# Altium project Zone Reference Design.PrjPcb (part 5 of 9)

## Sheet TPS1214-Q1.SchDoc
size 431 x 279 mm; Date: Not shown in title block; ApprovedBy: Not shown in title block; CheckedBy: Not shown in title block; Author: Not shown in title block; CompanyName: Not shown in title block; Engineer: Not shown in title block; Organization: Not shown in title block; Address1: Not shown in title block; Address2: Not shown in title block; Address3: Not shown in title block; Address4: Not shown in title block; DocumentNumber: 1; Revision: Use project parameter SCH_Rev; SheetNumber: 19; SheetTotal: 30; PageSetup: Record=PageOptions¦CenterHorizontal=True¦CenterVertical=True¦PrintScale=1.00¦XCorrection=1.00¦YCorrection=1.00¦PrintKind=0¦BorderSize=5000000¦LeftOffset=0¦BottomOffset=0¦Orientation=2¦PaperLength=1000¦PaperWidth=1000¦Scale=100¦PaperSource=15¦PrintQuality=600¦MediaType=1¦DitherType=10¦PaperKind=Letter¦PrintScaleMode=1
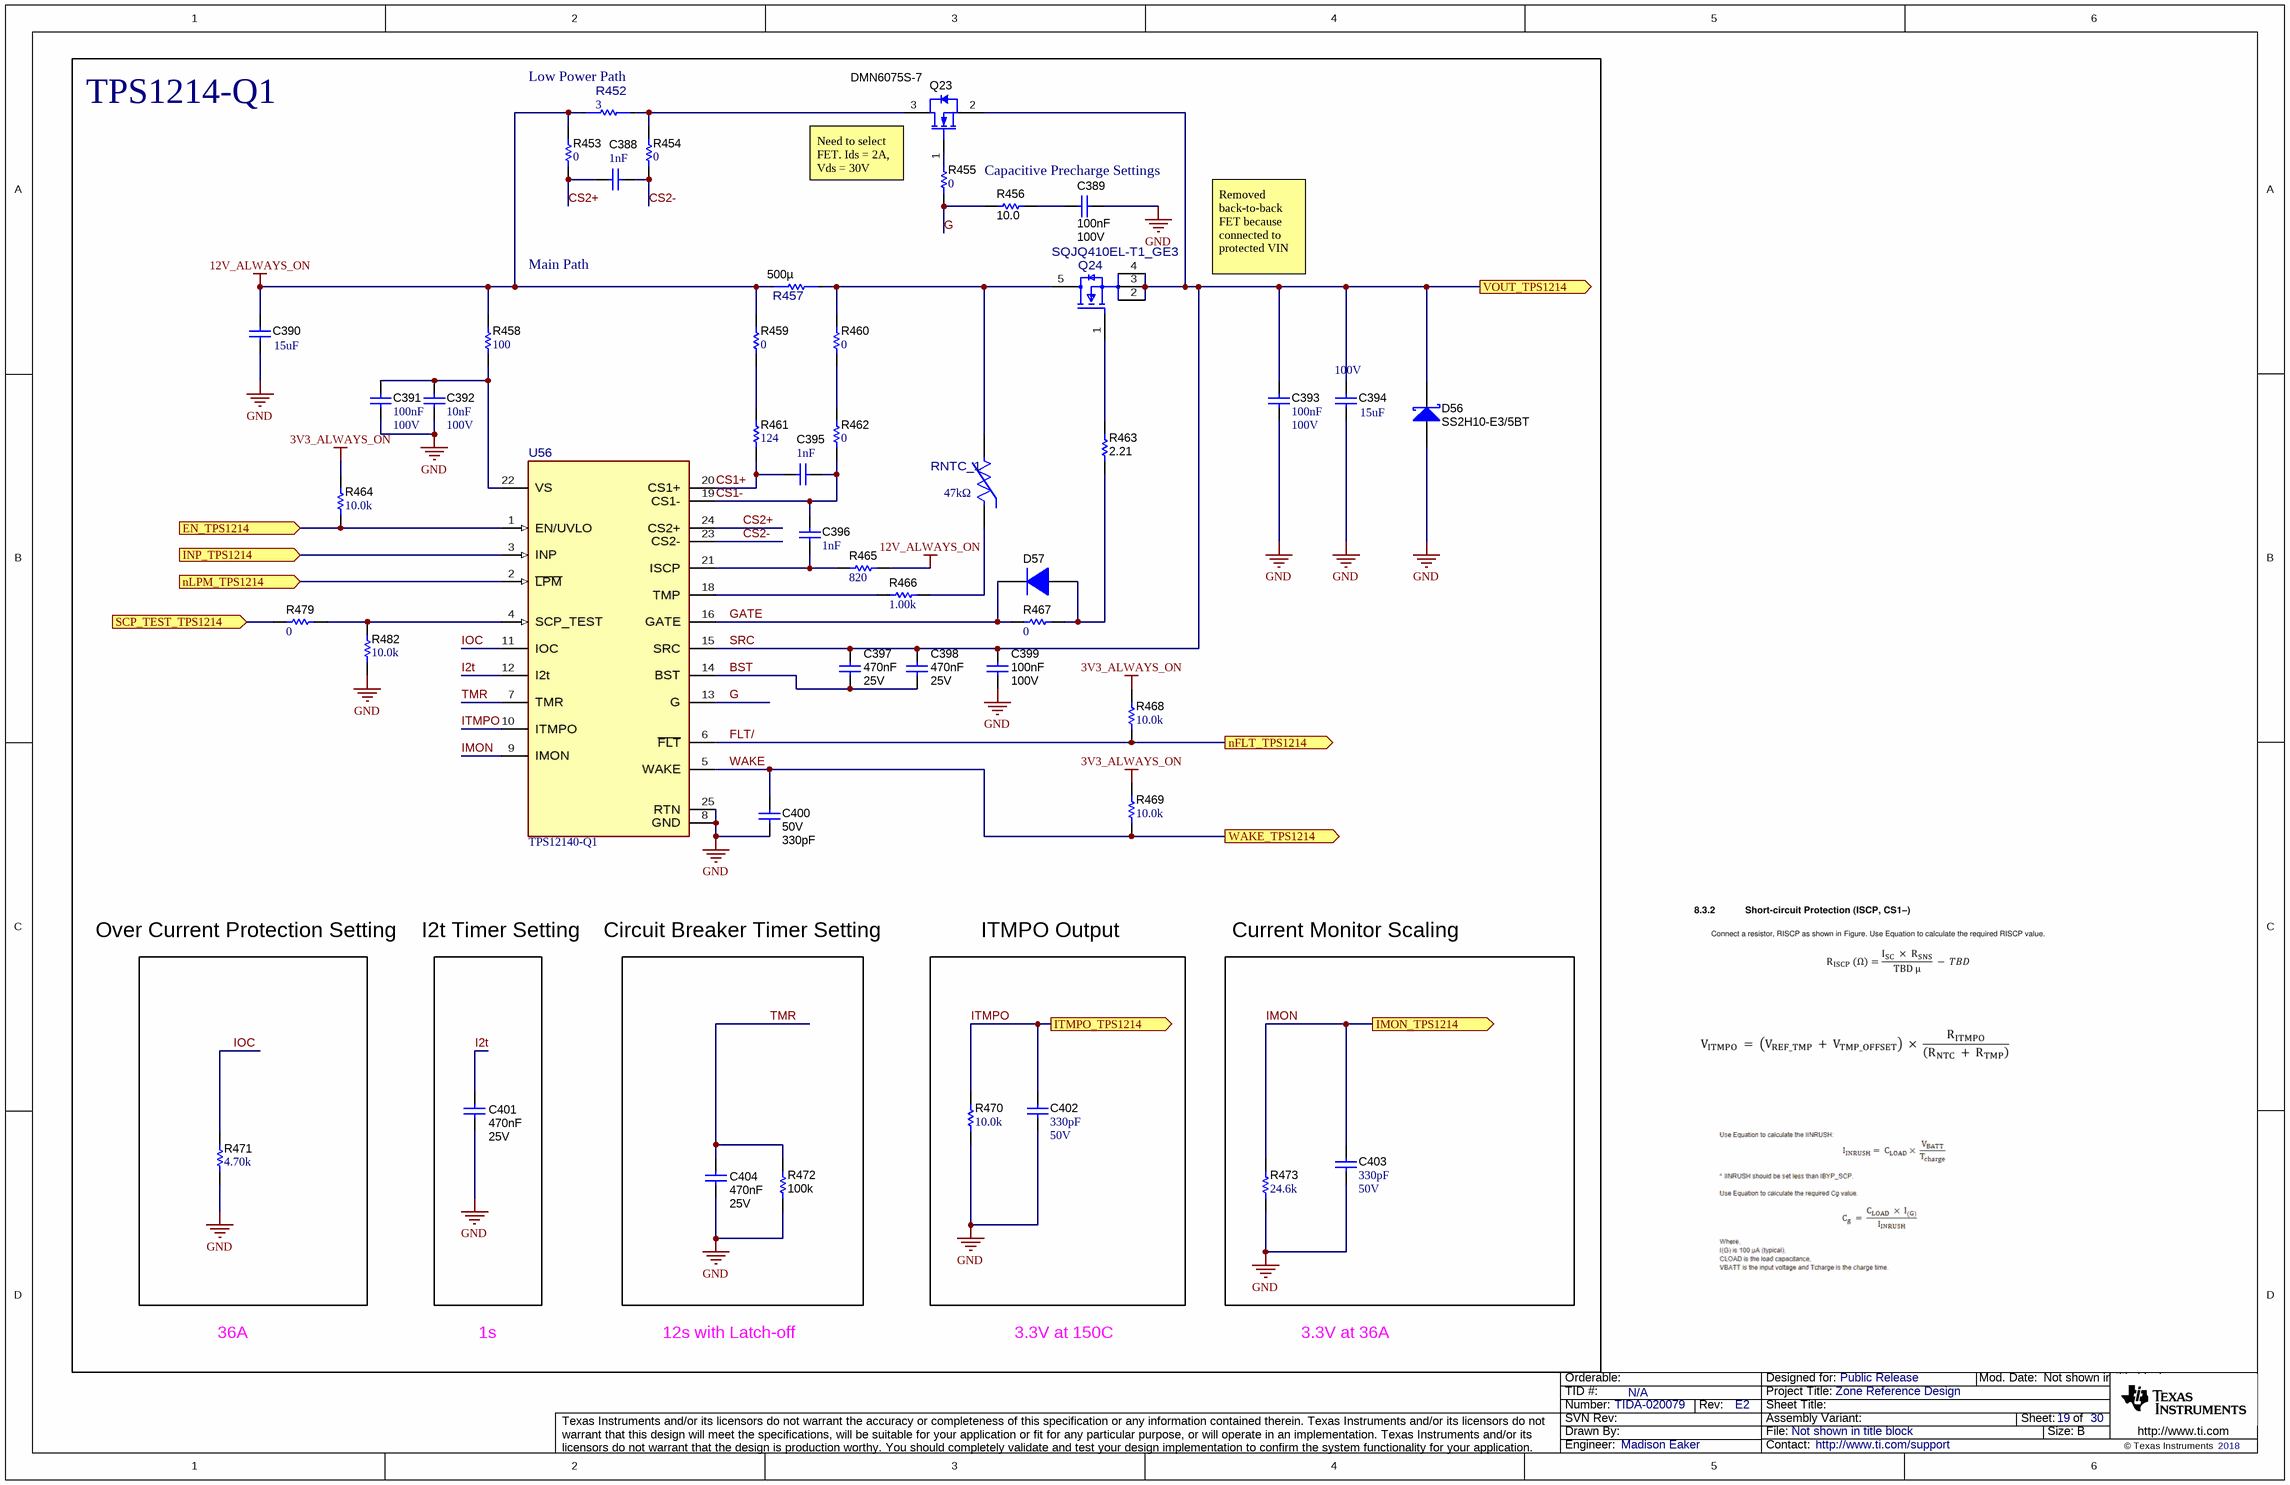
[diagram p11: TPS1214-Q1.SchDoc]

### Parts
C388  Cap_F: 1nF  [0603]  (hidden comment: C0603X102K5RACTU)
C389  Cap_F: 100nF  VDC_V: 100V  [0805_HV]  (hidden comment: CGA4J2X7R2A104K125AA)
C390  ValueDisplayed: 15uF  [KCM55W]  (hidden comment: KCM55WR72A156MH01K)
C391  Cap_F: 100nF  VDC_V: 100V  [0603]  (hidden comment: HMK107B7104KAHT)
C392  Cap_F: 10nF  VDC_V: 100V  [0603]  (hidden comment: CGA3E2X7R2A103K080AA)
C393  Cap_F: 100nF  VDC_V: 100V  [0603]  (hidden comment: HMK107B7104KAHT)
C394  Value2: 100V  ValueDisplayed: 15uF  [KCM55W]  (hidden comment: KCM55WR72A156MH01K)
C395  Cap_F: 1nF  [0603]  (hidden comment: C0603X102K5RACTU)
C396  Cap_F: 1nF  [0603]  (hidden comment: C0603X102K5RACTU)
C397  Cap_F: 470nF  VDC_V: 25V  [0603]  (hidden comment: CGA3E3X7R1E474K080AB)
C398  Cap_F: 470nF  VDC_V: 25V  [0603]  (hidden comment: CGA3E3X7R1E474K080AB)
C399  Cap_F: 100nF  VDC_V: 100V  [0805_HV]  (hidden comment: CGA4J2X7R2A104K125AA)
C400  VDC_V: 50V  ValueDisplayed: 330pF  [0402]  (hidden comment: GRM155R71H331KA01D)
C401  Cap_F: 470nF  VDC_V: 25V  [0603]  (hidden comment: CGA3E3X7R1E474K080AB)
C402  Cap_F: 330pF  VDC_V: 50V  [0603]  (hidden comment: C0603C331K5RACTU)
C403  Cap_F: 330pF  VDC_V: 50V  [0603]  (hidden comment: C0603C331K5RACTU)
C404  Cap_F: 470nF  VDC_V: 25V  [0603]  (hidden comment: CGA3E3X7R1E474K080AB)
D56  SS2H10-E3/5BT  [SMB]
D57  1N4148W-TP  [SOD-123]  (value not drawn)
Q23  DMN6075S-7  [SOT-23]
Q24  SQJQ410EL-T1_GE3  [FP-SQJQ410EL-T1_GE3_PowerPAK 8x8L-MFG]
R452  value 3  [FP-VMP-1R00-1.0-U_2010-MFG]  (hidden comment: VMP-1R00-1.0-U)
R453  ValueDisplayed: 0  [0603]  (hidden comment: CRCW06030000Z0EA)
R454  ValueDisplayed: 0  [0603]  (hidden comment: CRCW06030000Z0EA)
R455  ValueDisplayed: 0  [0603]  (hidden comment: CRCW06030000Z0EA)
R456  ValueDisplayed: 10.0  [0805_HV]  (hidden comment: RC0805FR-0710RL)
R457  Res_ohm: 500µ  [FP-WSL3921L5000FEA_3921-MFG]  (hidden comment: WSL3921L5000FEA)
R458  ValueDisplayed: 100  [0603]  (hidden comment: ERJ-3EKF1000V)
R459  ValueDisplayed: 0  [0603]  (hidden comment: CRCW06030000Z0EA)
R460  ValueDisplayed: 0  [0603]  (hidden comment: CRCW06030000Z0EA)
R461  ValueDisplayed: 124  [0603]  (hidden comment: RC0603FR-07124RL)
R462  ValueDisplayed: 0  [0603]  (hidden comment: CRCW06030000Z0EA)
R463  ValueDisplayed: 2.21  [0603]  (hidden comment: RC0603FR-072R21L)
R464  ValueDisplayed: 10.0k  [TNPW0603]  (hidden comment: TNPW060310K0BEEA)
R465  ValueDisplayed: 820  [0603]  (hidden comment: RC0603FR-07820RL)
R466  ValueDisplayed: 1.00k  [0603]  (hidden comment: RC0603FR-071KL)
R467  ValueDisplayed: 0  [0603]  (hidden comment: CRCW06030000Z0EA)
R468  ValueDisplayed: 10.0k  [TNPW0603]  (hidden comment: TNPW060310K0BEEA)
R469  ValueDisplayed: 10.0k  [TNPW0603]  (hidden comment: TNPW060310K0BEEA)
R470  ValueDisplayed: 10.0k  [0603]  (hidden comment: ERJ-3EKF1002V)
R471  ValueDisplayed: 4.70k  [0603]  (hidden comment: RC0603FR-074K7L)
R472  ValueDisplayed: 100k  [0603]  (hidden comment: CRCW0603100KFKEA)
R473  ValueDisplayed: 24.6k  [0603]  (hidden comment: RT0603BRD0724K6L)
R479  ValueDisplayed: 0  [0603]  (hidden comment: RC0603JR-070RL)
R482  ValueDisplayed: 10.0k  [TNPW0603]  (hidden comment: TNPW060310K0BEEA)
RNTC_1  value 47kΩ  [FP-NCU18WB473J6SRB_0603-MFG]  (hidden comment: NCU18WB473J6SRB)
U56  TPS12140-Q1  [RGE0023A-MFG]

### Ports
EN_TPS1214 (in), IMON_TPS1214 (out), INP_TPS1214 (in), ITMPO_TPS1214 (out), nFLT_TPS1214 (out), nLPM_TPS1214 (in), SCP_TEST_TPS1214 (in), VOUT_TPS1214 (out), WAKE_TPS1214 (out)

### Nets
3V3_ALWAYS_ON: R464.2 R468.2 R469.2
12V_ALWAYS_ON: C390.1 R452.1 R453.2 R457.1 R458.2 R459.2 R465.2
GND: C389.2 C390.2 C391.2 C392.2 C393.2 C394.2 C399.2 C400.2 C401.2 C402.2 C403.2 C404.2 D56.2(A) R470.2 R471.1 R472.1 R473.1 R482.1 U56.8(GND) U56.25(RTN)
BST: C397.2 C398.2 U56.14(BST)  [project net BST_19]
CS1+: C395.2 R461.1 U56.20(CS1+)  [project net CS1+_19]
CS1-: C395.1 C396.1 R462.1 U56.19(CS1-)  [project net CS1-_19]
CS2+: C388.2 R453.1 U56.24(CS2+)  [project net CS2+_19]
CS2-: C388.1 R454.1 U56.23(CS2-)  [project net CS2-_19]
EN_TPS1214: R464.1 U56.1(EN/UVLO) ; port EN_TPS1214
EPWM_15A: R479.1 ; port SCP_TEST_TPS1214
FLT/: R468.1 U56.6(~{FLT}) ; port nFLT_TPS1214
G: R455.1 R456.2 U56.13(G)  [project net G_19]
GATE: D57.1(K) R467.2 U56.16(GATE)  [project net GATE_19]
GPIO79: U56.3(INP) ; port INP_TPS1214
GPIO107: U56.2(~{LPM}) ; port nLPM_TPS1214
I2t: C401.1 U56.12(I2t)  [project net I2t_19]
IMON: C403.1 R473.2 U56.9(IMON) ; port IMON_TPS1214
IOC: R471.2 U56.11(IOC)  [project net IOC_19]
ITMPO: C402.1 R470.1 U56.10(ITMPO) ; port ITMPO_TPS1214
SRC: C393.1 C394.1 C397.1 C398.1 C399.1 D56.1(K) Q23.2(S) Q24.2(S) Q24.3(S) Q24.4(S) U56.15(SRC) ; port VOUT_TPS1214
TMR: C404.1 R472.2 U56.7(TMR)  [project net TMR_19]
WAKE: C400.1 R469.1 U56.5(WAKE) ; port WAKE_TPS1214
NetC389_1: C389.1 R456.1
NetC391_1: C391.1 C392.1 R458.1 U56.22(VS)
NetC396_2: C396.2 R465.1 U56.21(ISCP)
NetD57_2: D57.2(A) R463.1 R467.1
NetQ23_1: Q23.1(G) R455.2
NetQ23_3: Q23.3(D) R452.2 R454.2
NetQ24_1: Q24.1(G) R463.2
NetQ24_5: Q24.5(D) R457.2 R460.2 RNTC_1.2
NetR459_1: R459.1 R461.2
NetR460_1: R460.1 R462.2
NetR466_1: R466.1 U56.18(TMP)
NetR466_2: R466.2 RNTC_1.1
NetR479_2: R479.2 R482.2 U56.4(SCP_TEST)

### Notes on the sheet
- (near R452) Low Power Path
- TPS1214-Q1
- Need to select FET. Ids = 2A, Vds = 30V
- Capacitive Precharge Settings
- Main Path
- Removed back-to-back FET because connected to protected VIN
- Over Current Protection Setting
- I2t Timer Setting
- Circuit Breaker Timer Setting
- ITMPO Output
- Current Monitor Scaling
- 36A
- 1s
- 12s with Latch-off
- 3.3V at 150C
- 3.3V at 36A

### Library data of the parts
C388 C395 C396 = CMP-0006976-5: CAP, CERM, 1000 pF, 50 V, +/- 10%, X7R, 0603; Manufacturer: Kemet; TaMin_C: -55°C; Polarized: N; SizeAreaWB_mm2: 4.68; Value1: Unknown; U/M: EA; Value: 1000pF; TaMax_C: 125°C; SizeZ_mm: 1; SizeX_mm: 1.6; SizeY_mm: 0.8; Value2: 50V; SizeArea_mm2: 1.28; AEC Category: Q200
C389 C399 = CMP-0007969-2: CAP, CERM, 0.1 uF, 100 V, +/- 10%, X7R, AEC-Q200 Grade 1, 0805; Manufacturer: TDK; TaMin_C: -55°C; ESR_ohm: 0.020726; Polarized: N; SizeAreaWB_mm2: 6.75; Value1: 0.020726 ohm; U/M: EA; Value: 0.1uF; TaMax_C: 125°C; SizeZ_mm: 1.45; SizeX_mm: 2; SizeY_mm: 1.25; Cap_Case: 0805; SizeArea_mm2: 2.5; AEC Qualified: Y; IRMS_A: 1.456A; AEC Grade: 1; AEC Category: Q200
C390 = CMP-0009477-2: CAP, CERM, 15 uF, 100 V, +/- 20%, X7R, Stacked 2220; Manufacturer: MuRata; TaMin_C: -55°C; Polarized: N; SizeAreaWB_mm2: 59.13; Value1: Unknown; U/M: EA; Value: 15uF; TaMax_C: 125°C; SizeZ_mm: 6.7; SizeX_mm: 6.1; SizeY_mm: 5.3; Cap_Case: 2220; Value2: 100V; SizeArea_mm2: 32.33; Cap_F: 15µF; AEC Category: Q200
C391 C393 = CMP-0081011-1: CAP, CERM, 0.1 µF, 100 V,+/- 10%, X7R, AEC-Q200 Grade 1, 0603; Manufacturer: Taiyo Yuden; SizeAreaWB_mm2: 4.68; SizeArea_mm2: 1.28; AEC Qualified: Y; AEC Category: Q200; Value: 0.1uF; TaMax_C: 125°C; SizeZ_mm: 1; Polarized: N; TaMin_C: -55°C; SizeY_mm: 0.8; U/M: EA; SizeX_mm: 1.6; ValueDisplayed: 0.1µF
C392 = CMP-0007082-4: CAP, CERM, 0.01 uF, 100 V, +/- 10%, X7R, AEC-Q200 Grade 1, 0603; Manufacturer: TDK; TaMin_C: -55°C; ESR_ohm: 0.2354; Polarized: N; SizeAreaWB_mm2: 4.68; Value1: 0.235428 ohm; U/M: EA; Value: 0.01uF; TaMax_C: 125°C; SizeZ_mm: 1; SizeX_mm: 1.6; SizeY_mm: 0.8; SizeArea_mm2: 1.28; AEC Qualified: Y; IRMS_A: 396.995mA; AEC Category: Q200
C394 = CMP-0009477-2: CAP, CERM, 15 uF, 100 V, +/- 20%, X7R, Stacked 2220; Manufacturer: MuRata; TaMin_C: -55°C; Polarized: N; SizeAreaWB_mm2: 59.13; Value1: Unknown; U/M: EA; Value: 15uF; TaMax_C: 125°C; SizeZ_mm: 6.7; SizeX_mm: 6.1; SizeY_mm: 5.3; Cap_Case: 2220; SizeArea_mm2: 32.33; Cap_F: 15µF; AEC Category: Q200
C397 C398 C401 C404 = CMP-0007092-5: CAP, CERM, 0.47 uF, 25 V, +/- 10%, X7R, AEC-Q200 Grade 1, 0603; Manufacturer: TDK; TaMin_C: -55°C; Polarized: N; SizeAreaWB_mm2: 4.68; Value1: Unknown; U/M: EA; Value: 0.47uF; TaMax_C: 125°C; SizeZ_mm: 1; SizeX_mm: 1.6; SizeY_mm: 0.8; SizeArea_mm2: 1.28; AEC Qualified: Y; AEC Category: Q200
C400 = CMP-0006687-2: CAP, CERM, 330 pF, 50 V, +/- 10%, X7R, 0402; Manufacturer: MuRata; TaMin_C: -55°C; Polarized: N; SizeAreaWB_mm2: 3; Value1: Unknown; U/M: EA; Value: 330pF; TaMax_C: 125°C; SizeZ_mm: 0.6; SizeX_mm: 1; SizeY_mm: 0.5; AEC Category: Q200
C402 C403 = CMP-0006921-4: CAP, CERM, 330 pF, 50 V, +/- 10%, X7R, 0603; Manufacturer: Kemet; TaMin_C: -55°C; Polarized: N; SizeAreaWB_mm2: 4.68; Value1: Unknown; U/M: EA; Value: 330pF; TaMax_C: 125°C; SizeZ_mm: 1; SizeX_mm: 1.6; SizeY_mm: 0.8; SizeArea_mm2: 1.28; AEC Category: Q200
D56 = CMP-0028987-2: Diode, Schottky, 100 V, 2 A, SMB; Manufacturer: Vishay-Semiconductor; Vf_V: 790mV; AEC Qualified: N; SizeArea_mm2: 21.336; Value: 100V; SizeX_mm: 5.6; Value1: 2A; Value2: 0.79V; SizeZ_mm: 2.6; SizeAreaWB_mm2: 44.156; AEC Category: Q101; TJmax_C: 175°C; SizeY_mm: 3.81
D57 = CMP-0076974-1: Diode, Switching, 100 V, 0.15 A, SOD-123; Manufacturer: Micro Commercial Components; SizeAreaWB_mm2: 13.095; Vr_V: 100V; SizeArea_mm2: 6.545; TJmax_C: 150°C; AEC Category: Q101; Value: 100V; SizeZ_mm: 1.35; Green_REACh: Incomplete; Io_A: 150mA; Vf_V: 1.25V; SizeY_mm: 1.7; Green_Lifecycle: Not Set; U/M: EA; Value1: 0.15A; SizeX_mm: 3.85
Q23 = CMP-0078323-1: MOSFET, N-CH, 60 V, 2 A, AEC-Q101, SOT-23; Manufacturer: Diodes Inc.; Alternate Manufacturer: None; ChType: N; QgTyp_nC: 5.6; SizeAreaWB_mm2: 14; SizeArea_mm2: 7.5; IdsMax_A: 2A; AEC Qualified: Y; VdsMax_V: 60V; Rdson45_ohm: 0.12; Vgs_V: 20V; AEC Category: Q101; Value: 60V; SizeZ_mm: 1.1; SizeY_mm: 3; Value2: 5.6 nC; U/M: EA; Value1: 0.12 ohm; SizeX_mm: 2.5
Q24 = CMP-0091832-1: N-Channel 100V 135A (Tc) 136W (Tc) Surface Mount PowerPAK® 8 x 8; Manufacturer: Vishay; Rthja Max: 50°C/W; Rdson45_ohm: 2.8m; AEC Qualified: Yes; QgTyp_nC: 97nC @ 10V; Standoff Height: 0mm; Input Capacitace At Vds: 5620pF @ 25V; Threshold Vgs Min: 1.5V; SizeZ_mm: 2.03mm; Turn On Delay Time: 19ns; Typ Forward Diode Voltage: 0.83V; TJmax_C: +175°C; AEC Grade: Grade 0; Transconductance: 84S; Number Of N Channels: 1; Turn Off Delay Time: 69ns; Pulse Drain Current: 210A; ChMode: False; Threshold Vgs Max: 2.5V; Vgs_V: 20V; VdsMax_V: 1.2V
R452 = CMP-0098465-1: 1 Ohms ±1% 3W Chip Resistor 2010 (5025 Metric) Automotive AEC-Q200, Current Sense, Moisture Resistant, Pulse Withstanding; Manufacturer: Isabellenhuette; AEC Grade: Grade 0; AEC Qualified: Yes; Res_ohm: 1; SizeZ_mm: 0.55mm; TempCo: 20ppm/°C
R453-R455 R459 R460 R462 R467 = CMP-0025697-4: RES, 0, 5%, 0.1 W, AEC-Q200 Grade 0, 0603; Manufacturer: Vishay-Dale; Power_W: 100mW; TempCo: 200 ppm/C; Value_Code: 0000; Value: 0; EIA_Code: E24; SizeX_mm: 1.6; SizeY_mm: 0.8; SizeZ_mm: 1; Value2: 0.1W; SizeArea_mm2: 1.28; CompType: Resistor; AEC Qualified: Y; VDC_V: 75V; AEC Category: Q200
R456 = CMP-0021863-2: RES, 10.0, 1%, 0.125 W, 0805; Manufacturer: Yageo America; Power_W: 125mW; TempCo: 200 ppm/C; Value_Code: 10R0; U/M: EA; Value: 10.0; EIA_Code: E96; Res_ohm: 10; SizeX_mm: 2; SizeY_mm: 1.25; SizeZ_mm: 1.45; Value2: 0.125W; SizeArea_mm2: 2.5; VDC_V: 150V; AEC Category: Q200
R457 = CMP-0092921-1: Res Metal Strip 3921 0.0005 Ohm 1% 3W ±175ppm/°C Molded SMD SMD Embossed Plastic T/R; Manufacturer: Vishay Dale; Value: 500µ; TempCo: 150ppm/°C; SizeZ_mm: 0.05inch; AEC Qualified: Yes; AEC Grade: Grade 0
R458 = CMP-0022679-3: RES, 100, 1%, 0.1 W, AEC-Q200 Grade 0, 0603; Manufacturer: Panasonic; Power_W: 100mW; TempCo: 100 ppm/C; Value_Code: 100R; U/M: EA; Value: 100; EIA_Code: E96; SizeX_mm: 1.6; SizeY_mm: 0.8; SizeZ_mm: 1; Value2: 0.1W; SizeArea_mm2: 1.28; AEC Qualified: Y; AEC Grade: 0; AEC Category: Q200
R461 = CMP-0022773-5: RES, 124, 1%, 0.1 W, 0603; Manufacturer: Yageo; Power_W: 100mW; TempCo: 100 ppm/C; Value_Code: 124R; Value: 124; EIA_Code: E96; SizeX_mm: 1.6; SizeY_mm: 0.8; SizeZ_mm: 1; Value2: 0.1W; SizeArea_mm2: 1.28; AEC Qualified: N; VDC_V: 75V; AEC Category: Q200; SizeAreaWB_mm2: 4.68
R463 = CMP-0023007-4: RES, 2.21, 1%, 0.1 W, 0603; Manufacturer: Yageo; Power_W: 100mW; TempCo: 200 ppm/C; Value_Code: 2R21; Value: 2.21; EIA_Code: E96; SizeX_mm: 1.6; SizeY_mm: 0.8; SizeZ_mm: 1; Value2: 0.1W; SizeArea_mm2: 1.28; AEC Qualified: N; VDC_V: 75V; AEC Category: Q200; SizeAreaWB_mm2: 4.68
R464 R468 R469 R482 = CMP-0025686-1: RES, 10.0 k, 0.1%, 0.1 W, AEC-Q200 Grade 1, 0603; Manufacturer: Vishay-Dale; Power_W: 100mW; TempCo: 25 ppm/C; Value_Code: 10k0; U/M: EA; Value: 10.0k; EIA_Code: E192; Res_ohm: 10k; SizeX_mm: 1.6; SizeY_mm: 0.85; SizeZ_mm: 0.55; Value2: 0.1W; SizeArea_mm2: 1.36; AEC Qualified: Y; VDC_V: 75V; AEC Grade: 1; AEC Category: Q200
R465 = CMP-0023288-5: RES, 820, 1%, 0.1 W, 0603; Manufacturer: Yageo; Power_W: 100mW; TempCo: 100 ppm/C; Value_Code: 820R; Value: 820; SizeX_mm: 1.6; SizeY_mm: 0.8; SizeZ_mm: 1; Value2: 0.1W; SizeArea_mm2: 1.28; AEC Qualified: N; VDC_V: 75V; AEC Category: Q200; SizeAreaWB_mm2: 4.68
R466 = CMP-0022895-5: RES, 1.00 k, 1%, 0.1 W, 0603; Manufacturer: Yageo; Power_W: 100mW; TempCo: 100 ppm/C; Value_Code: 1k00; Value: 1.00k; EIA_Code: E96; Res_ohm: 1k; SizeX_mm: 1.6; SizeY_mm: 0.8; SizeZ_mm: 1; Value2: 0.1W; SizeArea_mm2: 1.28; AEC Qualified: N; VDC_V: 75V; AEC Category: Q200; SizeAreaWB_mm2: 4.68
R470 = CMP-0022684-2: RES, 10.0 k, 1%, 0.1 W, 0603; Manufacturer: Panasonic; Power_W: 100mW; TempCo: 100 ppm/C; Value_Code: 10k0; U/M: EA; Value: 10.0k; EIA_Code: E96; Res_ohm: 10k; SizeX_mm: 1.6; SizeY_mm: 0.8; SizeZ_mm: 1; Value2: 0.1W; SizeArea_mm2: 1.28; VDC_V: 75V; AEC Category: Q200
R471 = CMP-0023153-5: RES, 4.70 k, 1%, 0.1 W, 0603; Manufacturer: Yageo; Power_W: 100mW; TempCo: 100 ppm/C; Value_Code: 4k70; Value: 4.70k; Res_ohm: 4.7k; SizeX_mm: 1.6; SizeY_mm: 0.8; SizeZ_mm: 1; Value2: 0.1W; SizeArea_mm2: 1.28; AEC Qualified: N; VDC_V: 75V; AEC Category: Q200; SizeAreaWB_mm2: 4.68
R472 = CMP-0021990-4: RES, 100 k, 1%, 0.1 W, AEC-Q200 Grade 0, 0603; Manufacturer: Vishay-Dale; Power_W: 100mW; TempCo: 100 ppm/C; Value: 100k; EIA_Code: E96; SizeX_mm: 1.6; SizeY_mm: 0.8; SizeZ_mm: 1; Value2: 0.1W; SizeArea_mm2: 1.28; AEC Qualified: Y; VDC_V: 75V; AEC Category: Q200; AEC Grade: 0
R473 = CMP-0023989-3: RES, 24.6 k, 0.1%, 0.1 W, 0603; Manufacturer: Yageo America; Power_W: 100mW; TempCo: 25 ppm/C; Value_Code: 24k6; U/M: EA; Value: 24.6k; EIA_Code: E192; SizeX_mm: 1.6; SizeY_mm: 0.8; SizeZ_mm: 1; Value2: 0.1W; SizeArea_mm2: 1.28; VDC_V: 75V; AEC Category: Q200
R479 = CMP-0025885-5: RES, 0, 5%, 0.1 W, 0603; Manufacturer: Yageo; Power_W: 100mW; TempCo: 200 ppm/C; Value_Code: 0000; Value: 0; EIA_Code: E24; SizeX_mm: 1.6; SizeZ_mm: 1; Value2: 0.1W; SizeArea_mm2: 1.28; AEC Qualified: N; VDC_V: 75V; AEC Category: Q200; SizeY_mm: 0.8; SizeAreaWB_mm2: 4.68
RNTC_1 = CMP-0095715-1: NTC Thermistor for Temperature Sensor, Automotive, 0603, 47kΩ, 5%, 0.046mA, 5V; Manufacturer: Murata; B 25 50: 4050K; B 25 100: 4131K; SizeZ_mm: 0.95mm; AEC Qualified: Yes; B 25 85: 4108K; B Tolerance: 1%; Automotive Grade: Grade 0
U56 = CMP-0121394-1: Low IQ Smart High Side gate driver with I2t, Low Power Mode and Diagnostics; Manufacturer: Texas Instruments; SizeZ_mm: 1mm; Standoff Height: 0mm

## Sheet CAN-LIN Overview.SchDoc
size 431 x 279 mm; Date: Not shown in title block; ApprovedBy: Not shown in title block; CheckedBy: Not shown in title block; Author: Not shown in title block; CompanyName: Not shown in title block; Engineer: Not shown in title block; Organization: Not shown in title block; Address1: Not shown in title block; Address2: Not shown in title block; Address3: Not shown in title block; Address4: Not shown in title block; DocumentNumber: 1; Revision: Use project parameter SCH_Rev; SheetNumber: 20; SheetTotal: 30; PageSetup: Record=PageOptions¦CenterHorizontal=True¦CenterVertical=True¦PrintScale=1.00¦XCorrection=1.00¦YCorrection=1.00¦PrintKind=0¦BorderSize=5000000¦LeftOffset=0¦BottomOffset=0¦Orientation=2¦PaperLength=1000¦PaperWidth=1000¦Scale=100¦PaperSource=15¦PrintQuality=600¦MediaType=1¦DitherType=10¦PaperKind=Letter¦PrintScaleMode=1
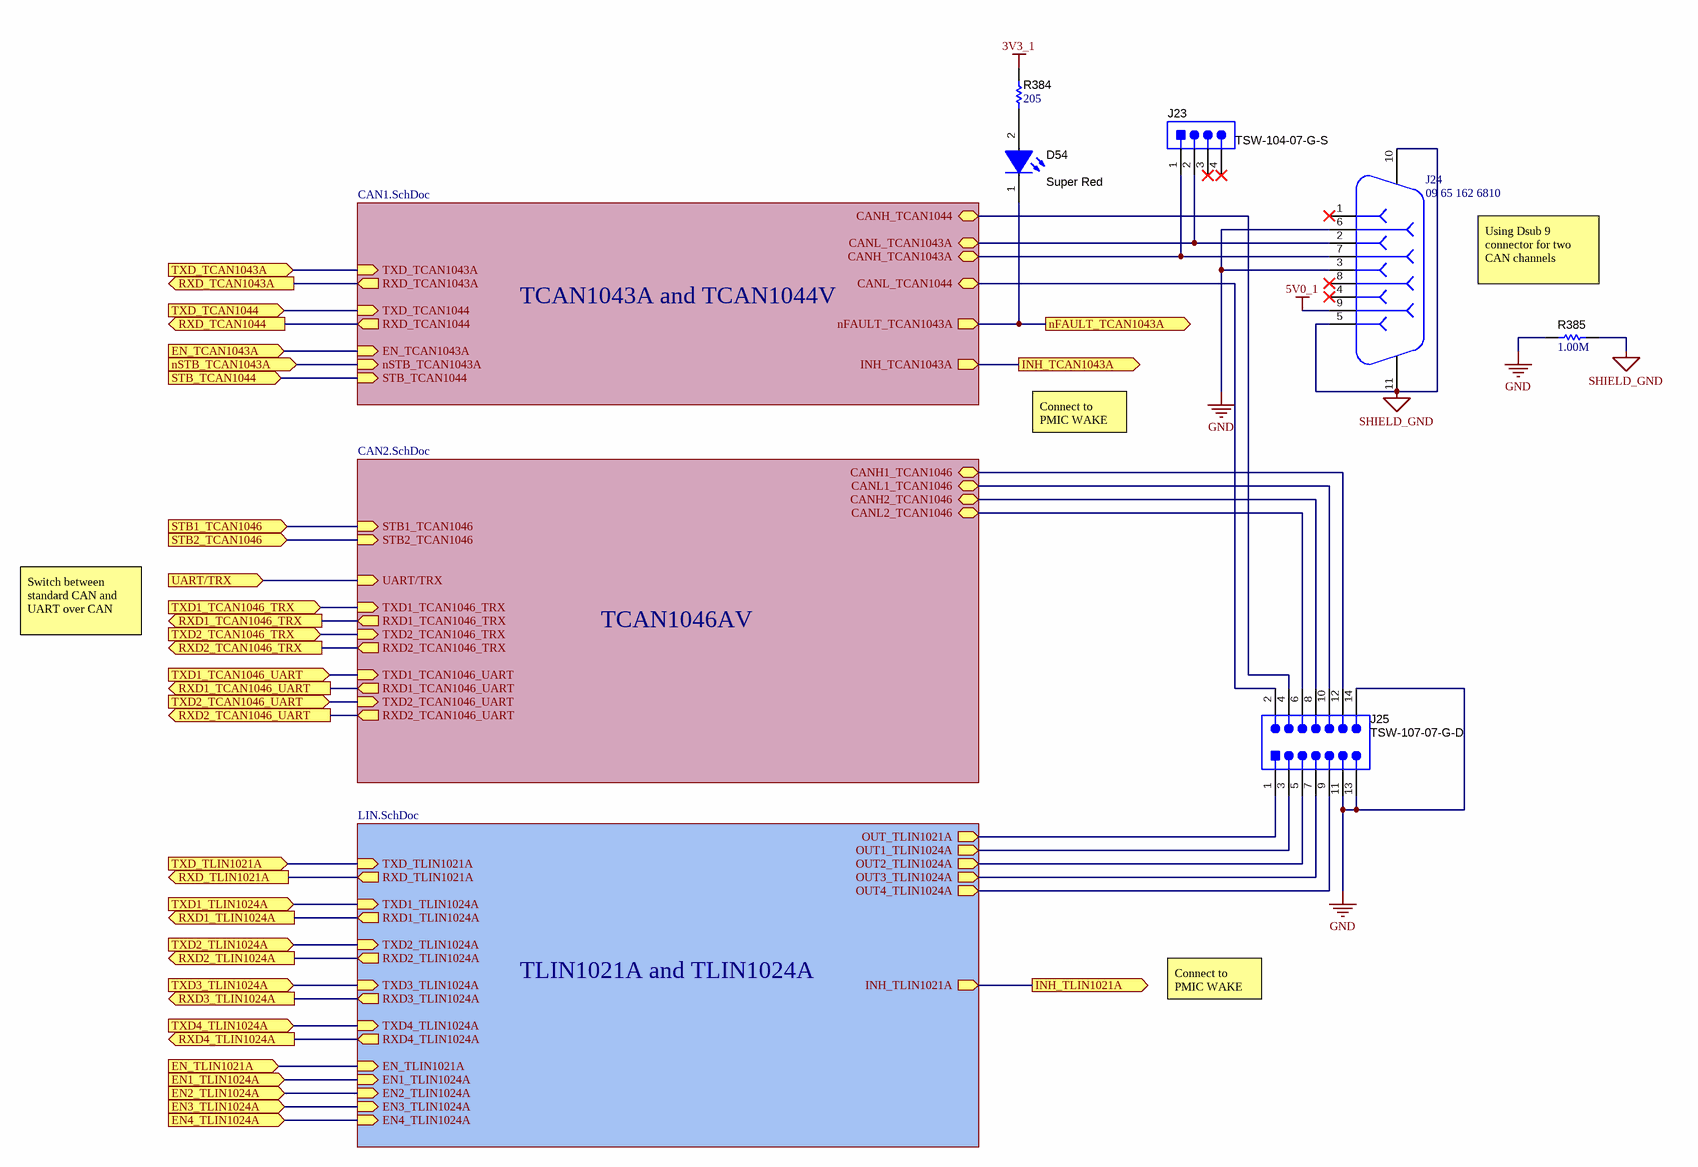
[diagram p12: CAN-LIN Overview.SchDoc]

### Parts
D54  value Super Red  [WL-SMCW_RED]  (hidden comment: 150060SS75000)
J23  TSW-104-07-G-S  [TSW-104-07-G-S]
J24  09 65 162 6810  [Harting_09 65 162 6810]
J25  TSW-107-07-G-D  [TSW-107-07-X-D]
R384  ValueDisplayed: 205  [0603]  (hidden comment: RC0603FR-07205RL)
R385  ValueDisplayed: 1.00M  [0603]  (hidden comment: MCT06030C1004FP500)

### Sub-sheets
TCAN1043A and TCAN1044V = CAN1.SchDoc: TXD_TCAN1044 (in), RXD_TCAN1044 (out), STB_TCAN1044 (in), TXD_TCAN1043A (in), INH_TCAN1043A (out), nFAULT_TCAN1043A (out), nSTB_TCAN1043A (in), EN_TCAN1043A (in), RXD_TCAN1043A (out), CANH_TCAN1043A (bidir), CANL_TCAN1043A (bidir), CANH_TCAN1044 (bidir), CANL_TCAN1044 (bidir)
TCAN1046AV = CAN2.SchDoc: STB1_TCAN1046 (in), STB2_TCAN1046 (in), TXD1_TCAN1046_UART (in), TXD1_TCAN1046_TRX (in), RXD1_TCAN1046_UART (out), RXD1_TCAN1046_TRX (out), TXD2_TCAN1046_UART (in), TXD2_TCAN1046_TRX (in), RXD2_TCAN1046_UART (out), RXD2_TCAN1046_TRX (out), UART/TRX (in), CANH1_TCAN1046 (bidir), CANL1_TCAN1046 (bidir), CANH2_TCAN1046 (bidir), CANL2_TCAN1046 (bidir)
TLIN1021A and TLIN1024A = LIN.SchDoc: EN_TLIN1021A (in), TXD_TLIN1021A (in), RXD_TLIN1021A (out), INH_TLIN1021A (out), EN1_TLIN1024A (in), EN2_TLIN1024A (in), RXD1_TLIN1024A (out), RXD2_TLIN1024A (out), TXD1_TLIN1024A (in), TXD2_TLIN1024A (in), RXD3_TLIN1024A (out), RXD4_TLIN1024A (out), TXD3_TLIN1024A (in), TXD4_TLIN1024A (in), EN3_TLIN1024A (in), EN4_TLIN1024A (in), OUT_TLIN1021A (out), OUT1_TLIN1024A (out), OUT2_TLIN1024A (out), OUT3_TLIN1024A (out), OUT4_TLIN1024A (out)

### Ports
EN1_TLIN1024A (in), EN2_TLIN1024A (in), EN3_TLIN1024A (in), EN4_TLIN1024A (in), EN_TCAN1043A (in), EN_TLIN1021A (in), INH_TCAN1043A (out), INH_TLIN1021A (out), nFAULT_TCAN1043A (out), nSTB_TCAN1043A (in), RXD1_TCAN1046_TRX (out), RXD1_TCAN1046_UART (out), RXD1_TLIN1024A (out), RXD2_TCAN1046_TRX (out), RXD2_TCAN1046_UART (out), RXD2_TLIN1024A (out), RXD3_TLIN1024A (out), RXD4_TLIN1024A (out), RXD_TCAN1043A (out), RXD_TCAN1044 (out), RXD_TLIN1021A (out), STB1_TCAN1046 (in), STB2_TCAN1046 (in), STB_TCAN1044 (in), TXD1_TCAN1046_TRX (in), TXD1_TCAN1046_UART (in), TXD1_TLIN1024A (in), TXD2_TCAN1046_TRX (in), TXD2_TCAN1046_UART (in), TXD2_TLIN1024A (in), TXD3_TLIN1024A (in), TXD4_TLIN1024A (in), TXD_TCAN1043A (in), TXD_TCAN1044 (in), TXD_TLIN1021A (in), UART/TRX (in)

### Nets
3V3_1: R384.2
5V0_1: J24.9
GND: J24.3 J24.6 J25.11 J25.13 J25.14 R385.1
SHIELD_GND: J24.5 J24.10 J24.11 R385.2
CAN1_1046_N: J25.10 ; sheet TCAN1046AV/CANL1_TCAN1046
CAN1_1046_P: J25.12 ; sheet TCAN1046AV/CANH1_TCAN1046
CAN2_1046_N: J25.6 ; sheet TCAN1046AV/CANL2_TCAN1046
CAN2_1046_P: J25.8 ; sheet TCAN1046AV/CANH2_TCAN1046
CAN2_RXD: port RXD_TCAN1044, sheet TCAN1043A and TCAN1044V/RXD_TCAN1044
CAN2_TXD: port TXD_TCAN1044, sheet TCAN1043A and TCAN1044V/TXD_TCAN1044
CAN5_RXD: port RXD2_TCAN1046_TRX, sheet TCAN1046AV/RXD2_TCAN1046_TRX
CAN5_TXD: port TXD2_TCAN1046_TRX, sheet TCAN1046AV/TXD2_TCAN1046_TRX
CAN6_RXD: port RXD1_TCAN1046_TRX, sheet TCAN1046AV/RXD1_TCAN1046_TRX
CAN6_TXD: port TXD1_TCAN1046_TRX, sheet TCAN1046AV/TXD1_TCAN1046_TRX
CAN7_RXD: port RXD_TCAN1043A, sheet TCAN1043A and TCAN1044V/RXD_TCAN1043A
CAN7_TXD: port TXD_TCAN1043A, sheet TCAN1043A and TCAN1044V/TXD_TCAN1043A
CAN_1043_N: J23.2 J24.2 ; sheet TCAN1043A and TCAN1044V/CANL_TCAN1043A
CAN_1043_P: J23.1 J24.7 ; sheet TCAN1043A and TCAN1044V/CANH_TCAN1043A
CAN_1044_N: J25.2 ; sheet TCAN1043A and TCAN1044V/CANL_TCAN1044
CAN_1044_P: J25.4 ; sheet TCAN1043A and TCAN1044V/CANH_TCAN1044
EN1_TLIN1024A: port EN_TLIN1021A, port EN1_TLIN1024A, port EN2_TLIN1024A, port EN3_TLIN1024A, port EN4_TLIN1024A, sheet TLIN1021A and TLIN1024A/EN_TLIN1021A, sheet TLIN1021A and TLIN1024A/EN1_TLIN1024A, sheet TLIN1021A and TLIN1024A/EN2_TLIN1024A, sheet TLIN1021A and TLIN1024A/EN3_TLIN1024A, sheet TLIN1021A and TLIN1024A/EN4_TLIN1024A
EN_TCAN1043A: port EN_TCAN1043A, sheet TCAN1043A and TCAN1044V/EN_TCAN1043A
EPWM6_A: D54.1(K) ; port nFAULT_TCAN1043A, sheet TCAN1043A and TCAN1044V/nFAULT_TCAN1043A
GPIO85: port nSTB_TCAN1043A, sheet TCAN1043A and TCAN1044V/nSTB_TCAN1043A
GPIO86: port STB_TCAN1044, port STB1_TCAN1046, port STB2_TCAN1046, sheet TCAN1043A and TCAN1044V/STB_TCAN1044, sheet TCAN1046AV/STB1_TCAN1046, sheet TCAN1046AV/STB2_TCAN1046
GPIO125: port UART/TRX, sheet TCAN1046AV/UART/TRX
INH_TCAN1043A: port INH_TCAN1043A, port INH_TLIN1021A, sheet TLIN1021A and TLIN1024A/INH_TLIN1021A, sheet TCAN1043A and TCAN1044V/INH_TCAN1043A
LIN0_RXD: port RXD4_TLIN1024A, sheet TLIN1021A and TLIN1024A/RXD4_TLIN1024A
LIN0_TXD: port TXD4_TLIN1024A, sheet TLIN1021A and TLIN1024A/TXD4_TLIN1024A
LIN1_RXD: port RXD_TLIN1021A, sheet TLIN1021A and TLIN1024A/RXD_TLIN1021A
LIN1_TXD: port TXD_TLIN1021A, sheet TLIN1021A and TLIN1024A/TXD_TLIN1021A
LIN2_RXD: port RXD1_TLIN1024A, sheet TLIN1021A and TLIN1024A/RXD1_TLIN1024A
LIN2_TXD: port TXD1_TLIN1024A, sheet TLIN1021A and TLIN1024A/TXD1_TLIN1024A
LIN3_RXD: port RXD2_TLIN1024A, sheet TLIN1021A and TLIN1024A/RXD2_TLIN1024A
LIN4_RXD: port RXD3_TLIN1024A, sheet TLIN1021A and TLIN1024A/RXD3_TLIN1024A
LIN4_TXD: port TXD3_TLIN1024A, sheet TLIN1021A and TLIN1024A/TXD3_TLIN1024A
OUT1_TLIN1024A: J25.3 ; sheet TLIN1021A and TLIN1024A/OUT1_TLIN1024A
OUT2_TLIN1024A: J25.5 ; sheet TLIN1021A and TLIN1024A/OUT2_TLIN1024A
OUT3_TLIN1024A: J25.7 ; sheet TLIN1021A and TLIN1024A/OUT3_TLIN1024A
OUT4_TLIN1024A: J25.9 ; sheet TLIN1021A and TLIN1024A/OUT4_TLIN1024A
OUT_TLIN1021A: J25.1 ; sheet TLIN1021A and TLIN1024A/OUT_TLIN1021A
PR0_PRU1_GPIO18: port TXD1_TCAN1046_UART, sheet TCAN1046AV/TXD1_TCAN1046_UART
PR0_PRU1_GPIO19: port RXD1_TCAN1046_UART, sheet TCAN1046AV/RXD1_TCAN1046_UART
RXD2_TCAN1046_UART: port RXD2_TCAN1046_UART, sheet TCAN1046AV/RXD2_TCAN1046_UART
SDFM_CLK2: port TXD2_TCAN1046_UART, sheet TCAN1046AV/TXD2_TCAN1046_UART
SPI0_CLK: port TXD2_TLIN1024A, sheet TLIN1021A and TLIN1024A/TXD2_TLIN1024A
NetD54_2: D54.2(A) R384.1

Not connected (* = marked no-connect by the designer): J23 3* 4*; J24 1* 4* 8*

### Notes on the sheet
- Using Dsub 9 connector for two CAN channels
- Connect to PMIC WAKE
- Switch between standard CAN and UART over CAN

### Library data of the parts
D54 = CMP-0002893-1: LED, Super Red, SMD; Manufacturer: Wurth Elektronik; Io_A: 20mA; Value1: W; U/M: EA; Vf_V: 1.9V; Type: AlInGaP
J23 = CMP-0075409-2: Header, 100mil, 4x1, Gold, TH; Manufacturer: Samtec; Pitch_mm: 2.54; Cert_VDE: N; Gender: Male; Cert_CSA: Y; Voltage_V: 550V; Green_REACh: Passed; Current_A: 6.3A; Green_Lifecycle: Active; Row_Count: 1
J24 = CMP-0055372-1: D-Sub-9, 11Pos, Male, TH; Manufacturer: Harting; CT: TRUE; CompType: D-Sub; CNHeader: FALSE
J25 = CMP-0075415-1: Header, 100mil, 7x2, Gold, TH; Manufacturer: Samtec; Pitch_mm: 2.54; Cert_VDE: N; Gender: Male; Cert_CSA: Y; Voltage_V: 550V; Green_REACh: Passed; Current_A: 6.3A; CT: False; Green_Lifecycle: Active; Row_Count: 2; CNHeader: True
R384 = CMP-0022904-5: RES, 205, 1%, 0.1 W, 0603; Manufacturer: Yageo; Power_W: 100mW; TempCo: 100 ppm/C; Value_Code: 205R; Value: 205; EIA_Code: E96; SizeX_mm: 1.6; SizeY_mm: 0.8; SizeZ_mm: 1; Value2: 0.1W; SizeArea_mm2: 1.28; AEC Qualified: N; VDC_V: 75V; AEC Category: Q200; SizeAreaWB_mm2: 4.68
R385 = CMP-0022731-2: RES, 1.00 M, 1%, 0.125 W, 0603; Manufacturer: Vishay/Beyschlag; Power_W: 125mW; TempCo: 50 ppm/C; Value_Code: 1M00; U/M: EA; Value: 1.00Meg; EIA_Code: E96; Res_ohm: 1M; SizeX_mm: 1.6; SizeY_mm: 0.8; SizeZ_mm: 1; Value2: 0.125W; SizeArea_mm2: 1.28; AEC Qualified: N; VDC_V: 75V; AEC Category: Q200

## Sheet LIN.SchDoc
size 431 x 279 mm; Date: Not shown in title block; ApprovedBy: Not shown in title block; CheckedBy: Not shown in title block; Author: Not shown in title block; CompanyName: Not shown in title block; Engineer: Not shown in title block; Organization: Not shown in title block; Address1: Not shown in title block; Address2: Not shown in title block; Address3: Not shown in title block; Address4: Not shown in title block; DocumentNumber: 1; Revision: Use project parameter SCH_Rev; SheetNumber: 23; SheetTotal: 30; PageSetup: Record=PageOptions¦CenterHorizontal=True¦CenterVertical=True¦PrintScale=1.00¦XCorrection=1.00¦YCorrection=1.00¦PrintKind=0¦BorderSize=5000000¦LeftOffset=0¦BottomOffset=0¦Orientation=2¦PaperLength=1000¦PaperWidth=1000¦Scale=100¦PaperSource=15¦PrintQuality=600¦MediaType=1¦DitherType=10¦PaperKind=Letter¦PrintScaleMode=1
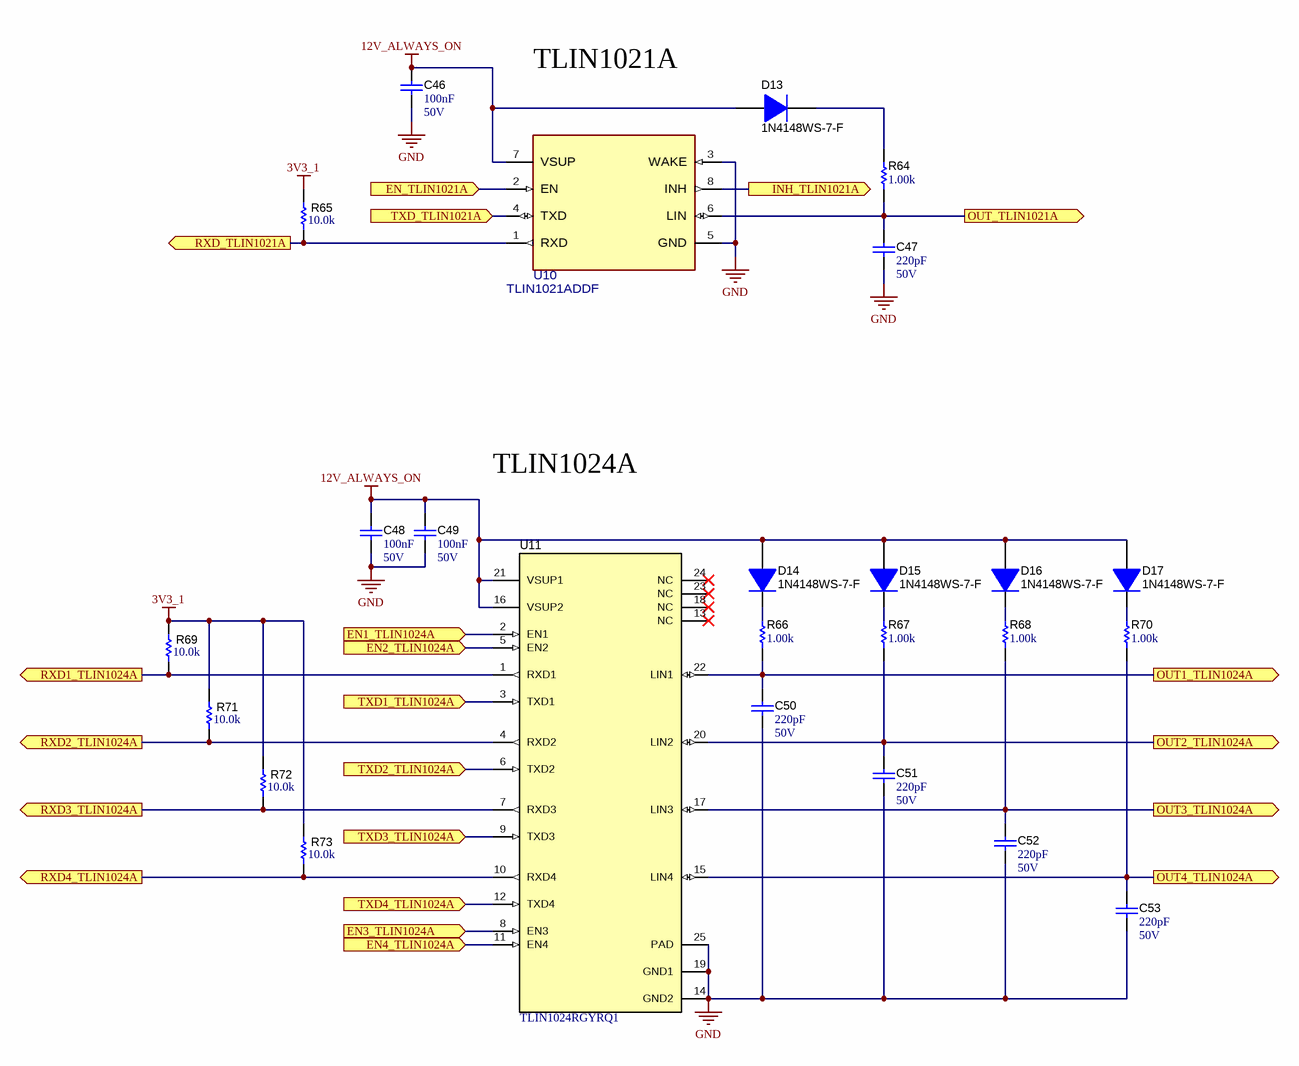
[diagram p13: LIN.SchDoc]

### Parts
C46  Cap_F: 100nF  VDC_V: 50V  [0603]  (hidden comment: 06035C104KAZ2A)
C47  Cap_F: 220pF  VDC_V: 50V  [0603]  (hidden comment: CL10B221JB8NNNC)
C48  Cap_F: 100nF  VDC_V: 50V  [0603]  (hidden comment: 06035C104KAZ2A)
C49  Cap_F: 100nF  VDC_V: 50V  [0603]  (hidden comment: 06035C104KAZ2A)
C50  Cap_F: 220pF  VDC_V: 50V  [0603]  (hidden comment: CL10B221JB8NNNC)
C51  Cap_F: 220pF  VDC_V: 50V  [0603]  (hidden comment: CL10B221JB8NNNC)
C52  Cap_F: 220pF  VDC_V: 50V  [0603]  (hidden comment: CL10B221JB8NNNC)
C53  Cap_F: 220pF  VDC_V: 50V  [0603]  (hidden comment: CL10B221JB8NNNC)
D13  1N4148WS-7-F  [SOD-323]
D14  1N4148WS-7-F  [SOD-323]
D15  1N4148WS-7-F  [SOD-323]
D16  1N4148WS-7-F  [SOD-323]
D17  1N4148WS-7-F  [SOD-323]
R64  ValueDisplayed: 1.00k  [0603]  (hidden comment: RT0603BRD071KL)
R65  ValueDisplayed: 10.0k  [0402]  (hidden comment: AC0402FR-0710KL)
R66  ValueDisplayed: 1.00k  [0603]  (hidden comment: RT0603BRD071KL)
R67  ValueDisplayed: 1.00k  [0603]  (hidden comment: RT0603BRD071KL)
R68  ValueDisplayed: 1.00k  [0603]  (hidden comment: RT0603BRD071KL)
R69  ValueDisplayed: 10.0k  [0402]  (hidden comment: AC0402FR-0710KL)
R70  ValueDisplayed: 1.00k  [0603]  (hidden comment: RT0603BRD071KL)
R71  ValueDisplayed: 10.0k  [0402]  (hidden comment: AC0402FR-0710KL)
R72  ValueDisplayed: 10.0k  [0402]  (hidden comment: AC0402FR-0710KL)
R73  ValueDisplayed: 10.0k  [0402]  (hidden comment: AC0402FR-0710KL)
U10  TLIN1021ADDF  [DDF0008A-MFG]
U11  TLIN1024RGYRQ1  [RGY0024C]

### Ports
EN1_TLIN1024A (in), EN2_TLIN1024A (in), EN3_TLIN1024A (in), EN4_TLIN1024A (in), EN_TLIN1021A (in), INH_TLIN1021A (out), OUT1_TLIN1024A (out), OUT2_TLIN1024A (out), OUT3_TLIN1024A (out), OUT4_TLIN1024A (out), OUT_TLIN1021A (out), RXD1_TLIN1024A (out), RXD2_TLIN1024A (out), RXD3_TLIN1024A (out), RXD4_TLIN1024A (out), RXD_TLIN1021A (out), TXD1_TLIN1024A (in), TXD2_TLIN1024A (in), TXD3_TLIN1024A (in), TXD4_TLIN1024A (in), TXD_TLIN1021A (in)

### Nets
3V3_1: R65.2 R69.2 R71.2 R72.2 R73.2
12V_ALWAYS_ON: C46.1 C48.1 C49.1 D13.2(A) D14.2(A) D15.2(A) D16.2(A) D17.2(A) U10.7(VSUP) U11.16(VSUP2) U11.21(VSUP1)
GND: C46.2 C47.2 C48.2 C49.2 C50.2 C51.2 C52.2 C53.2 U10.3(WAKE) U10.5(GND) U11.14(GND2) U11.19(GND1) U11.25(PAD)
EN1_TLIN1024A: U10.2(EN) U11.2(EN1) U11.5(EN2) U11.8(EN3) U11.11(EN4) ; port EN_TLIN1021A, port EN1_TLIN1024A, port EN2_TLIN1024A, port EN3_TLIN1024A, port EN4_TLIN1024A
INH_TCAN1043A: U10.8(INH) ; port INH_TLIN1021A
LIN0_RXD: R73.1 U11.10(RXD4) ; port RXD4_TLIN1024A
LIN0_TXD: U11.12(TXD4) ; port TXD4_TLIN1024A
LIN1_RXD: R65.1 U10.1(RXD) ; port RXD_TLIN1021A
LIN1_TXD: U10.4(TXD) ; port TXD_TLIN1021A
LIN2_RXD: R69.1 U11.1(RXD1) ; port RXD1_TLIN1024A
LIN2_TXD: U11.3(TXD1) ; port TXD1_TLIN1024A
LIN3_RXD: R71.1 U11.4(RXD2) ; port RXD2_TLIN1024A
LIN4_RXD: R72.1 U11.7(RXD3) ; port RXD3_TLIN1024A
LIN4_TXD: U11.9(TXD3) ; port TXD3_TLIN1024A
OUT1_TLIN1024A: C50.1 R66.1 U11.22(LIN1) ; port OUT1_TLIN1024A
OUT2_TLIN1024A: C51.1 R67.1 U11.20(LIN2) ; port OUT2_TLIN1024A
OUT3_TLIN1024A: C52.1 R68.1 U11.17(LIN3) ; port OUT3_TLIN1024A
OUT4_TLIN1024A: C53.1 R70.1 U11.15(LIN4) ; port OUT4_TLIN1024A
OUT_TLIN1021A: C47.1 R64.1 U10.6(LIN) ; port OUT_TLIN1021A
SPI0_CLK: U11.6(TXD2) ; port TXD2_TLIN1024A
NetD13_1: D13.1(K) R64.2
NetD14_1: D14.1(K) R66.2
NetD15_1: D15.1(K) R67.2
NetD16_1: D16.1(K) R68.2
NetD17_1: D17.1(K) R70.2

Not connected (* = marked no-connect by the designer): U11 13(NC)* 18(NC)* 23(NC)* 24(NC)*

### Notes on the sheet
- TLIN1021A
- TLIN1024A

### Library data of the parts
C46 C48 C49 = CMP-0079095-1: CAP, CERM, 0.1 µF, 50 V,+/- 10%, X7R, AEC-Q200 Grade 1, 0603; Manufacturer: AVX; SizeAreaWB_mm2: 4.68; SizeArea_mm2: 1.28; AEC Qualified: Y; AEC Category: Q200; Value: 0.1uF; TaMax_C: 125°C; SizeZ_mm: 1; Polarized: N; TaMin_C: -55°C; SizeY_mm: 0.8; U/M: EA; SizeX_mm: 1.6; ValueDisplayed: 0.1µF
C47 C50-C53 = CMP-0860329-1: CAP, CERM, 220 pF, 50 V,+/- 5%, X7R, 0603; Manufacturer: Samsung Electro-Mechanics; SizeX_mm: 1.6; U/M: EA; SizeZ_mm: 1; TaMin_C: -55°C; SizeArea_mm2: 1.28; SizeAreaWB_mm2: 4.68; SizeY_mm: 0.8; Value: 220pF; TaMax_C: 125°C; AEC Qualified: N; AEC Category: Q200
D13-D17 = CMP-0079597-2: Diode, Switching, 75 V, 0.15 A, AEC-Q101, SOD-323; Manufacturer: Diodes Inc.; SizeX_mm: 2.7; Vf_V: 1.25V; AEC Qualified: Y; SizeArea_mm2: 3.645; AEC Category: Q101; SizeAreaWB_mm2: 8.695; Io_A: 150mA; SizeZ_mm: 1; Value1: 0.15A; SizeY_mm: 1.35; TJmax_C: 150°C; Vr_V: 75V; Value: 75V
R64 R66-R68 R70 = CMP-0023919-1: RES, 1.00 k, 0.1%, 0.1 W, 0603; Manufacturer: Yageo America; Power_W: 100mW; TempCo: 25 ppm/C; Value_Code: 1k00; U/M: EA; Value: 1.00k; EIA_Code: E192; Res_ohm: 1k; SizeX_mm: 1.6; SizeY_mm: 0.8; SizeZ_mm: 1; Value2: 0.1W; SizeArea_mm2: 1.28; VDC_V: 75V; AEC Category: Q200
R65 R69 R71-R73 = CMP-0077731-1: RES, 10.0 k, 1%, 0.063 W, AEC-Q200 Grade 0, 0402; Manufacturer: Yageo America; Power_W: 63mW; TempCo: 100 ppm/C; Value_Code: 10k0; U/M: EA; Value: 10.0k; EIA_Code: E96; Res_ohm: 10k; SizeX_mm: 1.0; SizeY_mm: 0.5; SizeZ_mm: 0.6; Value2: 0.063W; AEC Qualified: Y; VDC_V: 50V; AEC Grade: 0; AEC Category: Q200
U10 = CMP-0088554-1: Local Interconnect Network (LIN) Transceiver with Local Wake and Inhibit; Manufacturer: Texas Instruments; Standoff Height: 0mm; Max Supply Voltage: 36V; SizeZ_mm: 1.1mm; Min Supply Voltage: 5.5V; TaMax_C: +125°C; TJmax_C: +150°C; Nominal Supply Current: 300-1200uA; TaMin_C: -40°C
U11 = CMP-0081959-1: Quad Local Interconnect Network (LIN) Transceiver with Dominant State Timeout, RGY0024C (VQFN-24); Alternate PartNumber: TLIN1024RGYTQ1; Alternate Manufacturer: Texas Instruments; SizeAreaWB_mm2: 41.25; Rating: Automotive; SizeZ_mm: 1; SizeX_mm: 3.5; SizeY_mm: 5.5; SizeArea_mm2: 19.25; CompType: IC; AEC Qualified: Y; AEC Category: Q200

## Sheet CAN1.SchDoc
size 431 x 279 mm; Date: Not shown in title block; ApprovedBy: Not shown in title block; CheckedBy: Not shown in title block; Author: Not shown in title block; CompanyName: Not shown in title block; Engineer: Not shown in title block; Organization: Not shown in title block; Address1: Not shown in title block; Address2: Not shown in title block; Address3: Not shown in title block; Address4: Not shown in title block; DocumentNumber: 1; Revision: Use project parameter SCH_Rev; SheetNumber: 21; SheetTotal: 30; PageSetup: Record=PageOptions¦CenterHorizontal=True¦CenterVertical=True¦PrintScale=1.00¦XCorrection=1.00¦YCorrection=1.00¦PrintKind=0¦BorderSize=5000000¦LeftOffset=0¦BottomOffset=0¦Orientation=2¦PaperLength=1000¦PaperWidth=1000¦Scale=100¦PaperSource=15¦PrintQuality=600¦MediaType=1¦DitherType=10¦PaperKind=Letter¦PrintScaleMode=1
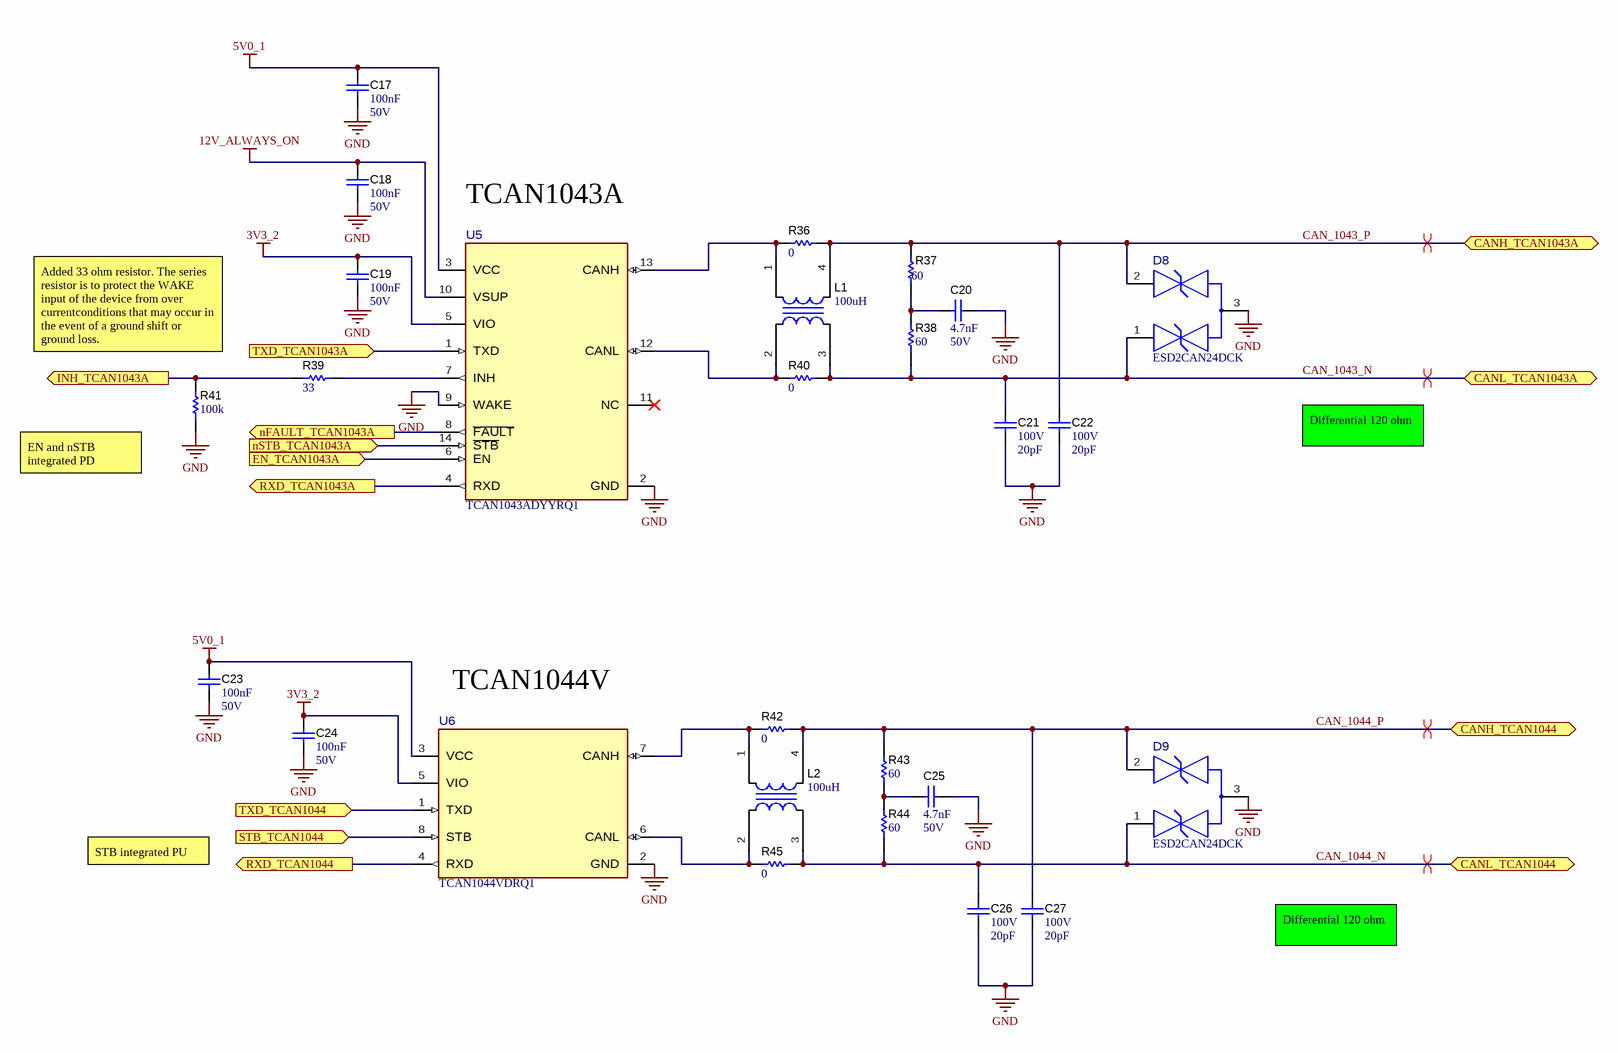
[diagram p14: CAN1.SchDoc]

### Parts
C17  Cap_F: 100nF  VDC_V: 50V  [0603]  (hidden comment: 06035C104KAZ2A)
C18  Cap_F: 100nF  VDC_V: 50V  [0603]  (hidden comment: 06035C104KAZ2A)
C19  Cap_F: 100nF  VDC_V: 50V  [0603]  (hidden comment: 06035C104KAZ2A)
C20  Cap_F: 4.7nF  VDC_V: 50V  [0603]  (hidden comment: C0603C472K5RACTU)
C21  VDC_V: 100V  ValueDisplayed: 20pF  [0805_HV]  (hidden comment: 08051A200JAT2A)
C22  VDC_V: 100V  ValueDisplayed: 20pF  [0805_HV]  (hidden comment: 08051A200JAT2A)
C23  Cap_F: 100nF  VDC_V: 50V  [0603]  (hidden comment: 06035C104KAZ2A)
C24  Cap_F: 100nF  VDC_V: 50V  [0603]  (hidden comment: 06035C104KAZ2A)
C25  Cap_F: 4.7nF  VDC_V: 50V  [0603]  (hidden comment: C0603C472K5RACTU)
C26  VDC_V: 100V  ValueDisplayed: 20pF  [0805_HV]  (hidden comment: 08051A200JAT2A)
C27  VDC_V: 100V  ValueDisplayed: 20pF  [0805_HV]  (hidden comment: 08051A200JAT2A)
D8  ESD2CAN24DCK  [DCK0003A-MFG]
D9  ESD2CAN24DCK  [DCK0003A-MFG]
L1  ValueDisplayed: 100uH  [ACT45B]  (hidden comment: ACT45B-101-2P-TL003)
L2  ValueDisplayed: 100uH  [ACT45B]  (hidden comment: ACT45B-101-2P-TL003)
R36  ValueDisplayed: 0  [0603]  (hidden comment: RC0603JR-070RL)
R37  ValueDisplayed: 60  [1206]  (hidden comment: CRCW120660R0KNEAIF)
R38  ValueDisplayed: 60  [1206]  (hidden comment: CRCW120660R0KNEAIF)
R39  ValueDisplayed: 33  [0603]  (hidden comment: CRCW060333R0JNEA)
R40  ValueDisplayed: 0  [0603]  (hidden comment: RC0603JR-070RL)
R41  ValueDisplayed: 100k  [0603]  (hidden comment: RG1608P-104-B-T5)
R42  ValueDisplayed: 0  [0603]  (hidden comment: RC0603JR-070RL)
R43  ValueDisplayed: 60  [1206]  (hidden comment: CRCW120660R0KNEAIF)
R44  ValueDisplayed: 60  [1206]  (hidden comment: CRCW120660R0KNEAIF)
R45  ValueDisplayed: 0  [0603]  (hidden comment: RC0603JR-070RL)
U5  TCAN1043ADYYRQ1  [DYY0014A-MFG]
U6  TCAN1044VDRQ1  [D0008A-MFG]

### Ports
CANH_TCAN1043A (bidir), CANH_TCAN1044 (bidir), CANL_TCAN1043A (bidir), CANL_TCAN1044 (bidir), EN_TCAN1043A (in), INH_TCAN1043A (out), nFAULT_TCAN1043A (out), nSTB_TCAN1043A (in), RXD_TCAN1043A (out), RXD_TCAN1044 (out), STB_TCAN1044 (in), TXD_TCAN1043A (in), TXD_TCAN1044 (in)

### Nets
3V3_2: C19.1 C24.1 U5.5(VIO) U6.5(VIO)
5V0_1: C17.1 C23.1 U5.3(VCC) U6.3(VCC)
12V_ALWAYS_ON: C18.1 U5.10(VSUP)
GND: C17.2 C18.2 C19.2 C20.1 C21.2 C22.2 C23.2 C24.2 C25.1 C26.2 C27.2 D8.3(GND) D9.3(GND) R41.1 U5.2(GND) U5.9(WAKE) U6.2(GND)
CAN2_RXD: U6.4(RXD) ; port RXD_TCAN1044
CAN2_TXD: U6.1(TXD) ; port TXD_TCAN1044
CAN7_RXD: U5.4(RXD) ; port RXD_TCAN1043A
CAN7_TXD: U5.1(TXD) ; port TXD_TCAN1043A
CAN_1043_N: C21.1 D8.1(1_IO) L1.3 R38.1 R40.2 ; port CANL_TCAN1043A
CAN_1043_P: C22.1 D8.2(2_IO) L1.4 R36.2 R37.2 ; port CANH_TCAN1043A
CAN_1044_N: C26.1 D9.1(1_IO) L2.3 R44.1 R45.2 ; port CANL_TCAN1044
CAN_1044_P: C27.1 D9.2(2_IO) L2.4 R42.2 R43.2 ; port CANH_TCAN1044
EN_TCAN1043A: U5.6(EN) ; port EN_TCAN1043A
EPWM6_A: U5.8(~{FAULT}) ; port nFAULT_TCAN1043A
GPIO85: U5.14(~{STB}) ; port nSTB_TCAN1043A
GPIO86: U6.8(STB) ; port STB_TCAN1044
INH_TCAN1043A: R39.1 R41.2 ; port INH_TCAN1043A
NetC20_2: C20.2 R37.1 R38.2
NetC25_2: C25.2 R43.1 R44.2
NetL1_1: L1.1 R36.1 U5.13(CANH)
NetL1_2: L1.2 R40.1 U5.12(CANL)
NetL2_1: L2.1 R42.1 U6.7(CANH)
NetL2_2: L2.2 R45.1 U6.6(CANL)
NetR39_2: R39.2 U5.7(INH)

Not connected (* = marked no-connect by the designer): U5 11(NC)*

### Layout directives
differential pair: CAN_1043_N, CAN_1043_P, CAN_1044_N, CAN_1044_P

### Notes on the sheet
- TCAN1043A
- (near R41) Added 33 ohm resistor. The series resistor is to protect the WAKE input of the device from over currentconditions that may occur in the event of a ground shift or ground loss.
- EN and nSTB integrated PD
- Differential 120 ohm
- TCAN1044V
- STB integrated PU

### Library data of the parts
C17-C19 C23 C24 = CMP-0079095-1: as C46 on sheet LIN
C20 C25 = CMP-0006943-2: CAP, CERM, 4700 pF, 50 V, +/- 10%, X7R, 0603; Manufacturer: Kemet; TaMin_C: -55°C; Polarized: N; SizeAreaWB_mm2: 4.68; Value1: Unknown; U/M: EA; Value: 4700pF; TaMax_C: 125°C; SizeZ_mm: 1; SizeX_mm: 1.6; SizeY_mm: 0.8; SizeArea_mm2: 1.28; AEC Category: Q200
C21 C22 C26 C27 = CMP-0007523-1: CAP, CERM, 20 pF, 100 V, +/- 5%, C0G/NP0, 0805; Manufacturer: AVX; TaMin_C: -55°C; ESR_ohm: 0.92; Polarized: N; SizeAreaWB_mm2: 6.75; Value1: 0.92 ohm; U/M: EA; Value: 20pF; TaMax_C: 125°C; SizeZ_mm: 1.45; SizeX_mm: 2; SizeY_mm: 1.25; Cap_Case: 0805; SizeArea_mm2: 2.5; AEC Category: Q200
D8 D9 = CMP-0093308-1: 24-V, 2-Channel ESD Protection Diode for In-Vehicle Networks, SC70-3; Manufacturer: Texas Instruments; Number Of Channels: 1; Breakdown Voltage: 25.5V; Cap_F: 3pF; TaMin_C: -55°C; AEC Qualified: No; Clamping Voltage: 32V; TaMax_C: +150°C; SizeZ_mm: 1.1mm; Ppk: 147W; Standoff Height: 0mm; VRWM: 24V; Direction: Bidirectional; Ipp: 3.5A
L1 L2 = CMP-0062430-2: Inductor, Ferrite, 100 uH, 0.15 A, 2 ohm, SMD; Manufacturer: TDK; Isat: 0.15A @ % inductance drop; Green_Lifecycle: Active; SizeAreaWB_mm2: 23.1; DCR_ohm: 2; Green_REACh: Passed; Value1: 2 ohm; Value: 100uH; Imax_A: 150mA; SizeZ_mm: 3; SizeX_mm: 4.5; SizeY_mm: 3.2; Value2: 0.15A; SizeArea_mm2: 14.4; Ind_H: 100µH; AEC Category: Q200
R36 R40 R42 R45 = CMP-0025885-5: as R479 on sheet TPS1214-Q1
R37 R38 R43 R44 = CMP-0018709-3: RES, 60, 10%, 0.25 W, AEC-Q200 Grade 0, 1206; Manufacturer: Vishay-Dale; Power_W: 250mW; TempCo: 200 ppm/C; Value_Code: 60R0; Value: 60; SizeX_mm: 3.2; SizeY_mm: 1.6; SizeZ_mm: 1.35; Value2: 0.25W; SizeArea_mm2: 5.12; AEC Qualified: Y; AEC Grade: 0; AEC Category: Q200
R39 = CMP-0025787-4: RES, 33, 5%, 0.1 W, AEC-Q200 Grade 0, 0603; Manufacturer: Vishay-Dale; Power_W: 100mW; TempCo: 200 ppm/C; Value_Code: 33R0; Value: 33; EIA_Code: E24; SizeX_mm: 1.6; SizeY_mm: 0.8; SizeZ_mm: 1; Value2: 0.1W; SizeArea_mm2: 1.28; AEC Qualified: Y; VDC_V: 75V; AEC Category: Q200; AEC Grade: 0
R41 = CMP-0023405-3: RES, 100 k, 0.1%, 0.1 W, 0603; Manufacturer: Susumu Co Ltd; Power_W: 100mW; TempCo: 25 ppm/C; U/M: EA; Value: 100k; EIA_Code: E192; SizeX_mm: 1.6; SizeY_mm: 0.8; SizeZ_mm: 1; Value2: 0.1W; SizeArea_mm2: 1.28; VDC_V: 75V; AEC Category: Q200
U5 = CMP-0089855-1: Low-Power Fault Protected CAN FD Transceiver with INH and WAKE; Manufacturer: Texas Instruments; Max Supply Voltage: 28V; Standoff Height: 0mm; Min Supply Voltage: 1.7V; AEC Grade: Grade 1; SizeZ_mm: 1.1mm; TJmax_C: +165°C; AEC Qualified: Yes
U6 = CMP-0032674-1: CAN Interface IC Automotive high speed CAN transceiver 8-SOIC -40 to 125; Manufacturer: Texas Instruments; SizeZ_mm: 1.75mm; AEC Qualified: No; Max Supply Voltage: 5.5V; Min Supply Voltage: 4.5V; Nominal Supply Current: 4.5-49mA; Standoff Height: 0.11mm; TaMax_C: +125°C; TaMin_C: -40°C; TJmax_C: +150°C

## Sheet CAN2.SchDoc
size 431 x 279 mm; Date: Not shown in title block; ApprovedBy: Not shown in title block; CheckedBy: Not shown in title block; Author: Not shown in title block; CompanyName: Not shown in title block; Engineer: Not shown in title block; Organization: Not shown in title block; Address1: Not shown in title block; Address2: Not shown in title block; Address3: Not shown in title block; Address4: Not shown in title block; DocumentNumber: 1; Revision: Use project parameter SCH_Rev; SheetNumber: 22; SheetTotal: 30; PageSetup: Record=PageOptions¦CenterHorizontal=True¦CenterVertical=True¦PrintScale=1.00¦XCorrection=1.00¦YCorrection=1.00¦PrintKind=0¦BorderSize=5000000¦LeftOffset=0¦BottomOffset=0¦Orientation=2¦PaperLength=1000¦PaperWidth=1000¦Scale=100¦PaperSource=15¦PrintQuality=600¦MediaType=1¦DitherType=10¦PaperKind=Letter¦PrintScaleMode=1
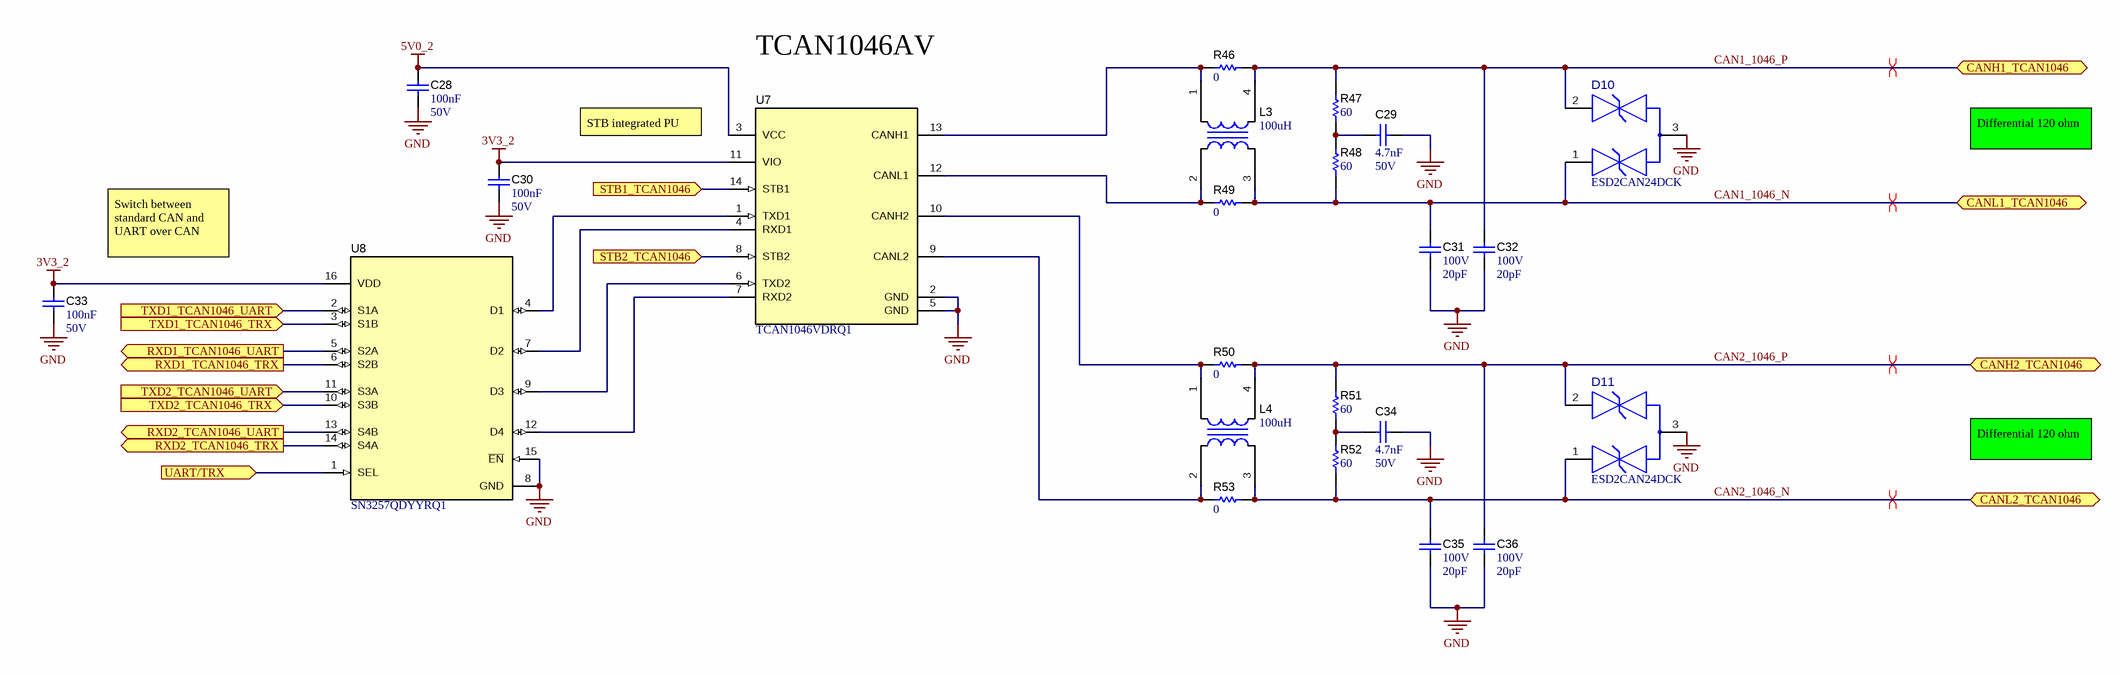
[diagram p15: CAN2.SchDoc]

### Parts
C28  Cap_F: 100nF  VDC_V: 50V  [0603]  (hidden comment: 06035C104KAZ2A)
C29  Cap_F: 4.7nF  VDC_V: 50V  [0603]  (hidden comment: C0603C472K5RACTU)
C30  Cap_F: 100nF  VDC_V: 50V  [0603]  (hidden comment: 06035C104KAZ2A)
C31  VDC_V: 100V  ValueDisplayed: 20pF  [0805_HV]  (hidden comment: 08051A200JAT2A)
C32  VDC_V: 100V  ValueDisplayed: 20pF  [0805_HV]  (hidden comment: 08051A200JAT2A)
C33  Cap_F: 100nF  VDC_V: 50V  [0603]  (hidden comment: 06035C104KAZ2A)
C34  Cap_F: 4.7nF  VDC_V: 50V  [0603]  (hidden comment: C0603C472K5RACTU)
C35  VDC_V: 100V  ValueDisplayed: 20pF  [0805_HV]  (hidden comment: 08051A200JAT2A)
C36  VDC_V: 100V  ValueDisplayed: 20pF  [0805_HV]  (hidden comment: 08051A200JAT2A)
D10  ESD2CAN24DCK  [DCK0003A-MFG]
D11  ESD2CAN24DCK  [DCK0003A-MFG]
L3  ValueDisplayed: 100uH  [ACT45B]  (hidden comment: ACT45B-101-2P-TL003)
L4  ValueDisplayed: 100uH  [ACT45B]  (hidden comment: ACT45B-101-2P-TL003)
R46  ValueDisplayed: 0  [0603]  (hidden comment: RC0603JR-070RL)
R47  ValueDisplayed: 60  [1206]  (hidden comment: CRCW120660R0KNEAIF)
R48  ValueDisplayed: 60  [1206]  (hidden comment: CRCW120660R0KNEAIF)
R49  ValueDisplayed: 0  [0603]  (hidden comment: RC0603JR-070RL)
R50  ValueDisplayed: 0  [0603]  (hidden comment: RC0603JR-070RL)
R51  ValueDisplayed: 60  [1206]  (hidden comment: CRCW120660R0KNEAIF)
R52  ValueDisplayed: 60  [1206]  (hidden comment: CRCW120660R0KNEAIF)
R53  ValueDisplayed: 0  [0603]  (hidden comment: RC0603JR-070RL)
U7  TCAN1046VDRQ1  [D0014A_N]
U8  SN3257QDYYRQ1  [DYY0016A]

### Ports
CANH1_TCAN1046 (bidir), CANH2_TCAN1046 (bidir), CANL1_TCAN1046 (bidir), CANL2_TCAN1046 (bidir), RXD1_TCAN1046_TRX (out), RXD1_TCAN1046_UART (out), RXD2_TCAN1046_TRX (out), RXD2_TCAN1046_UART (out), STB1_TCAN1046 (in), STB2_TCAN1046 (in), TXD1_TCAN1046_TRX (in), TXD1_TCAN1046_UART (in), TXD2_TCAN1046_TRX (in), TXD2_TCAN1046_UART (in), UART/TRX (in)

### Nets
3V3_2: C30.1 C33.1 U7.11(VIO) U8.16(VDD)
5V0_2: C28.1 U7.3(VCC)
GND: C28.2 C29.1 C30.2 C31.2 C32.2 C33.2 C34.1 C35.2 C36.2 D10.3(GND) D11.3(GND) U7.2(GND) U7.5(GND) U8.8(GND) U8.15(~{EN})
CAN1_1046_N: C31.1 D10.1(1_IO) L3.3 R48.1 R49.2 ; port CANL1_TCAN1046
CAN1_1046_P: C32.1 D10.2(2_IO) L3.4 R46.2 R47.2 ; port CANH1_TCAN1046
CAN2_1046_N: C35.1 D11.1(1_IO) L4.3 R52.1 R53.2 ; port CANL2_TCAN1046
CAN2_1046_P: C36.1 D11.2(2_IO) L4.4 R50.2 R51.2 ; port CANH2_TCAN1046
CAN5_RXD: U8.14(S4A) ; port RXD2_TCAN1046_TRX
CAN5_TXD: U8.10(S3B) ; port TXD2_TCAN1046_TRX
CAN6_RXD: U8.6(S2B) ; port RXD1_TCAN1046_TRX
CAN6_TXD: U8.3(S1B) ; port TXD1_TCAN1046_TRX
GPIO86: U7.8(STB2) U7.14(STB1) ; port STB1_TCAN1046, port STB2_TCAN1046
GPIO125: U8.1(SEL) ; port UART/TRX
PR0_PRU1_GPIO18: U8.2(S1A) ; port TXD1_TCAN1046_UART
PR0_PRU1_GPIO19: U8.5(S2A) ; port RXD1_TCAN1046_UART
RXD2_TCAN1046_UART: U8.13(S4B) ; port RXD2_TCAN1046_UART
SDFM_CLK2: U8.11(S3A) ; port TXD2_TCAN1046_UART
NetC29_2: C29.2 R47.1 R48.2
NetC34_2: C34.2 R51.1 R52.2
NetL3_1: L3.1 R46.1 U7.13(CANH1)
NetL3_2: L3.2 R49.1 U7.12(CANL1)
NetL4_1: L4.1 R50.1 U7.10(CANH2)
NetL4_2: L4.2 R53.1 U7.9(CANL2)
NetU7_1: U7.1(TXD1) U8.4(D1)
NetU7_4: U7.4(RXD1) U8.7(D2)
NetU7_6: U7.6(TXD2) U8.9(D3)
NetU7_7: U7.7(RXD2) U8.12(D4)

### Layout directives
differential pair: CAN1_1046_N, CAN1_1046_P, CAN2_1046_N, CAN2_1046_P

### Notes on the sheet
- TCAN1046AV
- STB integrated PU
- Differential 120 ohm
- Switch between standard CAN and UART over CAN

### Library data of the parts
C28 C30 C33 = CMP-0079095-1: as C46 on sheet LIN
C29 C34 = CMP-0006943-2: as C20 on sheet CAN1
C31 C32 C35 C36 = CMP-0007523-1: as C21 on sheet CAN1
D10 D11 = CMP-0093308-1: as D8 on sheet CAN1
L3 L4 = CMP-0062430-2: as L1 on sheet CAN1
R46 R49 R50 R53 = CMP-0025885-5: as R479 on sheet TPS1214-Q1
R47 R48 R51 R52 = CMP-0018709-3: as R37 on sheet CAN1
U7 = CMP-0013023-1: Automotive High Speed Dual CAN Transceiver, D0014A (SOIC-14); Manufacturer: Texas Instruments; SizeZ_mm: 1.75; SizeX_mm: 6; SizeY_mm: 8.65; SizeArea_mm2: 51.9; CompType: IC; U/M: EA; SizeAreaWB_mm2: 85.2
U8 = CMP-0860151-2: SN3257QDYYRQ1, DYY0016A (SOT-23-THIN-16); Manufacturer: Texas Instruments; SizeX_mm: 3.26; SizeArea_mm2: 13.692; SizeAreaWB_mm2: 22.152; AEC Qualified: Y; CompType: IC; SizeZ_mm: 1.1; AEC Category: Q200; SizeY_mm: 4.2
